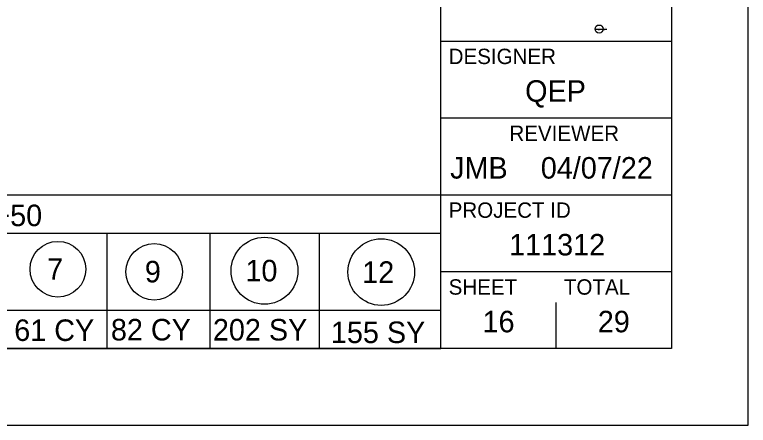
# Model space of a CAD drawing. Extents: x -433 to 34, y -184 to 22.
# Drawn here: x 29.226 to 34, y 0 to 2.671 of the extents above; entities that cross this region are included whole.
import ezdxf

# ---------------------------------------------------------------- set-up
doc = ezdxf.new("R2010")
doc.units = 0
for name, color, linetype in [('CS-ALGN-TEXT', 7, 'Continuous'), ('CS-ANNO', 7, 'Continuous'), ('CS-ANNO-MATC', 7, 'Continuous'), ('CS-ANNO-MATC-TEXT', 7, 'Continuous'), ('CS-ANNO-TABL', 7, 'Continuous')]:
    doc.layers.add(name, color=color, linetype=linetype)

msp = doc.modelspace()

# ---------------------------------------------------------------- linework, layer by layer
at = {"layer": 'CS-ALGN-TEXT'}
for p, q in [((25.0328, 1.5), (32, 1.5)), ((25.0328, 1.25), (32, 1.25)), ((29.8286, 0.5), (29.8286, 1.25)), ((30.498, 0.5), (30.498, 1.25)), ((31.2103, 0.5), (31.2103, 1.25)), ((32.75, 0.5), (32.75, 0.8)), ((25.0328, 0.75), (32, 0.75)), ((32.375, 0.675), (32.375, 0.675)), ((26.25, 0.5), (32, 0.5))]:
    msp.add_line(p, q, dxfattribs=at)
at = {"layer": 'CS-ANNO'}
msp.add_lwpolyline([(0, 0), (34, 0), (34, 22), (0, 22)], close=True, dxfattribs=at)
at = {"layer": 'CS-ANNO-MATC'}
for p, q in [((32, 0.5), (32, 21.5)), ((32, 2.5), (33.5, 2.5)), ((32, 2), (33.5, 2)), ((32, 1.5), (33.5, 1.5)), ((32, 1), (33.5, 1))]:
    msp.add_line(p, q, dxfattribs=at)
msp.add_lwpolyline([(1.5, 21.5), (33.5, 21.5), (33.5, 0.5), (1.5, 0.5)], close=True, dxfattribs=at)
at = {"layer": 'CS-ANNO-MATC-TEXT'}
for centre, radius in [((29.5077, 1.0156), 0.1813), ((30.8518, 1.0056), 0.2175), ((31.6114, 0.997), 0.2165), ((30.1339, 0.9989), 0.1837)]:
    msp.add_circle(centre, radius, dxfattribs=at)
at = {"layer": 'CS-ANNO-TABL'}
for p, q in [((33.0033, 2.5782), (33.0554, 2.5782)), ((33.0295, 2.5782), (33.079, 2.5782))]:
    msp.add_line(p, q, dxfattribs=at)
msp.add_circle((33.0293, 2.5782), 0.026, dxfattribs=at)

# ---------------------------------------------------------------- texts
at = {"layer": 'CS-ALGN-TEXT'}
for s, height, p in [('DESIGNER', 0.1, (32.05, 2.35)), ('QEP', 0.14, (32.5477, 2.105)), ('REVIEWER', 0.1, (32.4454, 1.85)), ('JMB', 0.14, (32.0596, 1.605)), ('04/07/22', 0.14, (32.6497, 1.605)), ('Sheet Totals 5+50 to 6+50', 0.14, (27.1984, 1.2956)), ('PROJECT ID', 0.1, (32.05, 1.35)), ('111312', 0.14, (32.4435, 1.105)), ('SHEET', 0.1, (32.05, 0.85)), ('TOTAL', 0.1, (32.8, 0.85)), ('16', 0.14, (32.2707, 0.605)), ('29', 0.14, (33.0206, 0.605))]:
    msp.add_text(s, height=height, dxfattribs=at).set_placement(p)
at = {"layer": 'CS-ANNO-MATC-TEXT'}
for s, p in [('7', (29.4377, 0.9466)), ('9', (30.0734, 0.9298)), ('10', (30.7277, 0.9365)), ('12', (31.4877, 0.9268)), ('61 CY', (29.2234, 0.5488)), ('82 CY', (29.8524, 0.5521)), ('202 SY', (30.5161, 0.5518)), ('155 SY', (31.2838, 0.5351))]:
    msp.add_text(s, height=0.14, dxfattribs=at).set_placement(p)
at = {"layer": 'CS-ANNO-TABL'}
for s, p in [('2', (33.0282, 2.5848)), ('Drawing', (33.0621, 2.5848)), ('6+00.00', (33.0213, 2.5684)), ('1:2', (33.0621, 2.5684))]:
    msp.add_text(s, height=0.00328, dxfattribs=at).set_placement(p)

doc.saveas('drawing.dxf')
